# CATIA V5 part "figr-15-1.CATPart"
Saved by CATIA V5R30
Part number: Part1
Bounding box of the stored display mesh (mm): x -92.657 to 112.488, y -68.408 to 38.341, z -24 to 61.972
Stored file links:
  D:\PROJECTS\CATIA V56R 2020\Resources\Parts File\c15_catia_v5_6r2020_prt\figr-15-1.CATPart
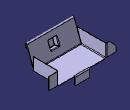
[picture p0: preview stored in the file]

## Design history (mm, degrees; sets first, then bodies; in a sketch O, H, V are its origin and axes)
SheetMetalParameters1: Thickness 1, BendRadius 2, KFactor 0.400515 {= log(min(100,max(20*SheetMetalParameters1.BendRadius,SheetMetalParameters1.Thickness)/SheetMetalParameters1.Thickness))/log(100)/2}, ReliefRadialLength 1, ReliefAxialLength 2, WallPerLength 50, MinimumBendRadius 0
Body1 (main body)
  Sketch1 on xy-plane, origin (0, 0, 0), H (1, 0, 0), V (0, 1, 0)
    line L1 (-62.6567, 37.3409) -> (82.4875, 37.3409)
    line L2 (82.4875, 37.3409) -> (82.4875, -38.1848)
    line L3 (82.4875, -38.1848) -> (-62.6567, -38.1848)
    line L4 (-62.6567, -38.1848) -> (-62.6567, 37.3409)
    horizontal: L1 H, L3 H
    vertical: L2 V, L4 V
  Wall1: Thickness 1, Profile Sketch1, OffsetValue 0
  d_NewWallOnEdge1: NewWallOnEdge_Length 25, NewWallOnEdge_HeightLimitOffset 0, NewWallOnEdge_WidthOffset1 -50, NewWallOnEdge_WidthOffset2 -50, NewWallOnEdge_Angle 90, NewWallOnEdge_BendRadiusValue 2 {= SheetMetalParameters1.BendRadius}, NewWallOnEdge_BendTable SheetMetalParameters1, NewWallOnEdge_Edge edge [face of Wall1 | face of Wall1], NewWallOnEdge_GapValue 0, KFacteur 0.400515 {= log(min(100,max(20*d_NewWallOnEdge1.Radius,SheetMetalParameters1.Thickness)/SheetMetalParameters1.Thickness))/log(100)/2}
  d_NewWallOnEdge2: NewWallOnEdge_Length 40, NewWallOnEdge_HeightLimitOffset 0, NewWallOnEdge_WidthOffset1 0, NewWallOnEdge_WidthOffset2 0, NewWallOnEdge_Angle 90, NewWallOnEdge_BendRadiusValue 2 {= SheetMetalParameters1.BendRadius}, NewWallOnEdge_BendTable SheetMetalParameters1, NewWallOnEdge_Edge edge [face of Wall1 | face of Wall1], NewWallOnEdge_GapValue 0, KFacteur 0.400515 {= log(min(100,max(20*d_NewWallOnEdge2.Radius,SheetMetalParameters1.Thickness)/SheetMetalParameters1.Thickness))/log(100)/2}
  d_NewWallOnEdge3: NewWallOnEdge_Length 30, NewWallOnEdge_HeightLimitOffset 0, NewWallOnEdge_WidthOffset1 0, NewWallOnEdge_WidthOffset2 0, NewWallOnEdge_Angle 90, NewWallOnEdge_BendRadiusValue 2 {= SheetMetalParameters1.BendRadius}, NewWallOnEdge_BendTable SheetMetalParameters1, NewWallOnEdge_Edge edge [face of d_NewWallOnEdge2 | face of d_NewWallOnEdge2], NewWallOnEdge_GapValue 0, KFacteur 0.400515 {= log(min(100,max(20*d_NewWallOnEdge3.Radius,SheetMetalParameters1.Thickness)/SheetMetalParameters1.Thickness))/log(100)/2}
  d_NewWallOnEdge4: NewWallOnEdge_Length 60, NewWallOnEdge_HeightLimitOffset 0, NewWallOnEdge_WidthOffset1 0, NewWallOnEdge_WidthOffset2 0, NewWallOnEdge_Angle 110, NewWallOnEdge_BendRadiusValue 2 {= SheetMetalParameters1.BendRadius}, NewWallOnEdge_BendTable SheetMetalParameters1, NewWallOnEdge_Edge edge [face of Wall1 | face of Wall1], NewWallOnEdge_GapValue 0, KFacteur 0.400515 {= log(min(100,max(20*d_NewWallOnEdge4.Radius,SheetMetalParameters1.Thickness)/SheetMetalParameters1.Thickness))/log(100)/2}
  Flange1: Angle 90, Length 10, Radius 2 {= SheetMetalParameters1.BendRadius}, KFacteur 0.400515 {= log(min(100,max(20*Flange1.Radius,SheetMetalParameters1.Thickness)/SheetMetalParameters1.Thickness))/log(100)/2}, Guide edge [face of d_NewWallOnEdge4 | face of d_NewWallOnEdge4]
  d_NewWallOnEdge5: NewWallOnEdge_Length 40, NewWallOnEdge_HeightLimitOffset 0, NewWallOnEdge_WidthLimit2 face of d_NewWallOnEdge4, NewWallOnEdge_WidthOffset1 0, NewWallOnEdge_WidthOffset2 -2, NewWallOnEdge_Angle 90, NewWallOnEdge_WithBend true, NewWallOnEdge_BendRadiusValue 2 {= SheetMetalParameters1.BendRadius}, NewWallOnEdge_BendTable SheetMetalParameters1, NewWallOnEdge_Edge edge [face of Wall1 | face of Wall1], NewWallOnEdge_GapValue 0, KFacteur 0.400515 {= log(min(100,max(20*d_NewWallOnEdge5.Radius,SheetMetalParameters1.Thickness)/SheetMetalParameters1.Thickness))/log(100)/2}
  d_NewWallOnEdge6: NewWallOnEdge_Length 30, NewWallOnEdge_HeightLimitOffset 0, NewWallOnEdge_WidthOffset1 0, NewWallOnEdge_WidthOffset2 0, NewWallOnEdge_Angle 90, NewWallOnEdge_BendRadiusValue 2 {= SheetMetalParameters1.BendRadius}, NewWallOnEdge_BendTable SheetMetalParameters1, NewWallOnEdge_Edge edge [face of d_NewWallOnEdge5 | face of d_NewWallOnEdge5], NewWallOnEdge_GapValue 0, KFacteur 0.400515 {= log(min(100,max(20*d_NewWallOnEdge6.Radius,SheetMetalParameters1.Thickness)/SheetMetalParameters1.Thickness))/log(100)/2}
  Chamfer1: ChamferAngle 45, ChamferLength1 20, ChamferLength2 0.5, ChamferPropagation 1, ChamferReverse false, ChamferType 1, CornerChamferEdges edge [face of d_NewWallOnEdge6 | face of d_NewWallOnEdge6]
  Corner1: CornerRadius 3, CornerChamferEdges (edge [face of d_NewWallOnEdge1 | face of d_NewWallOnEdge1]; edge [face of d_NewWallOnEdge1 | face of d_NewWallOnEdge1])
  Sketch2 on face of d_NewWallOnEdge4, origin (8.9154, -38.1848, 1), H (1, 0, 0), V (0, -0.342, 0.9397)
    line L1 (-12.2908, 45.4061) -> (12.3784, 45.4061)
    line L2 (12.3784, 45.4061) -> (12.3784, 21.719)
    line L3 (12.3784, 21.719) -> (-12.2908, 21.719)
    line L4 (-12.2908, 21.719) -> (-12.2908, 45.4061)
    horizontal: L1 H, L3 H
    vertical: L2 V, L4 V
  d_Stamp1: NewRoot_AttribNormalisation "No Standard", Stamp_FilletRadius 1, Stamp_IntersectFilletRadius 2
